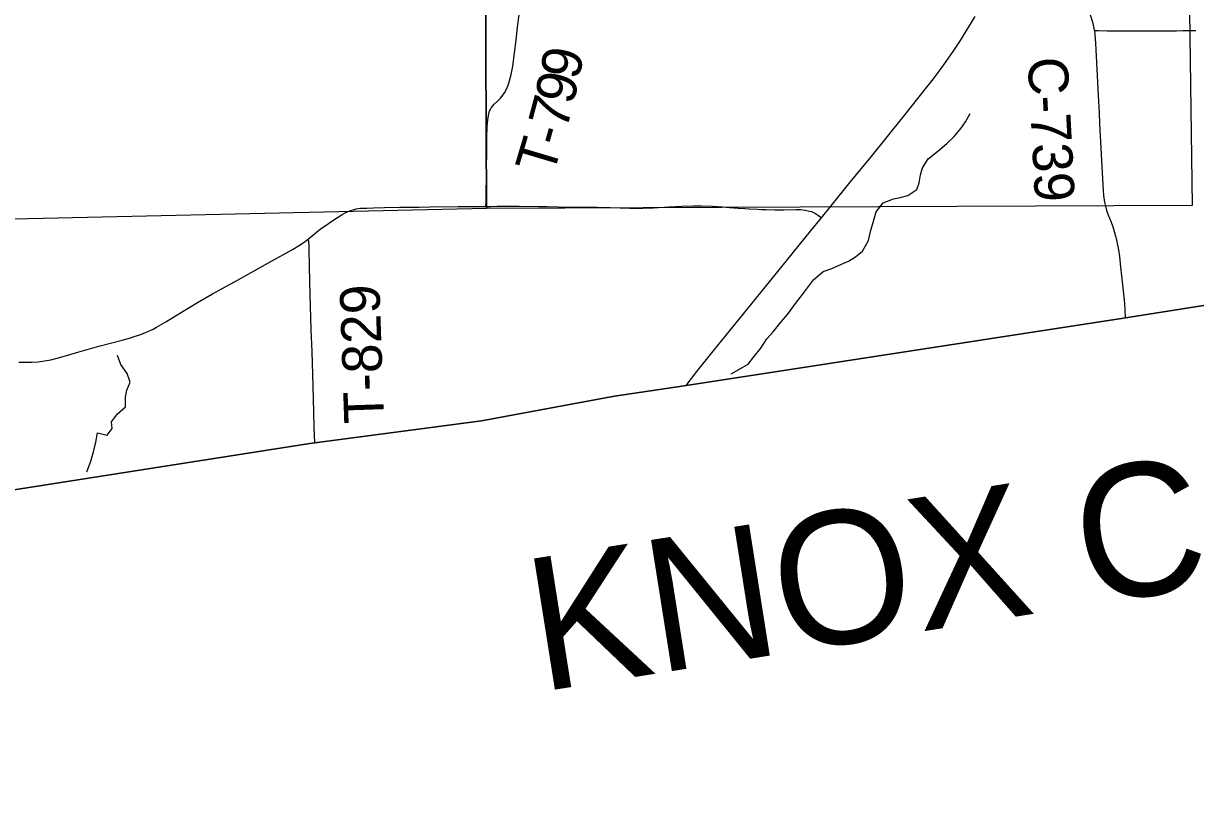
# Model space of a CAD drawing. Extents: x 1874609 to 2204689, y 815661 to 1281160.
# Drawn here: x 2026660 to 2035487, y 930213 to 936005 of the extents above; entities that cross this region are included whole.
import ezdxf

# ---------------------------------------------------------------- set-up
doc = ezdxf.new("R2010")
doc.units = 0
for name, color, linetype in [('GM_X_Adjacent_County', 7, 'Continuous'), ('GM_X_Adjacent_County_Text', 7, 'Continuous'), ('GM_X_County', 7, 'Continuous'), ('GM_X_County_Road', 7, 'Continuous'), ('GM_X_County_Road_Text', 7, 'Continuous'), ('GM_X_Minor_River', 7, 'Continuous'), ('GM_X_Section', 7, 'Continuous'), ('GM_X_State_Route', 7, 'Continuous'), ('GM_X_Township', 7, 'Continuous'), ('GM_X_Township_Road', 7, 'Continuous'), ('GM_X_Township_Road_Text', 7, 'Continuous')]:
    doc.layers.add(name, color=color, linetype=linetype)

msp = doc.modelspace()

# ---------------------------------------------------------------- linework, layer by layer
at = {"layer": 'GM_X_Adjacent_County'}
msp.add_lwpolyline([(2011234.5, 930213.3), (2013857.4, 930619.3), (2016073.2, 930958.1), (2016684.5, 931060.5), (2017738.3, 931178.7), (2023140.4, 931953.7), (2028815.8, 932841.3), (2030108.2, 933013.6), (2031110.9, 933197.6), (2031636.5, 933277.1), (2034944.9, 933785.2), (2038390.6, 934329.5), (2043970.6, 935214.4), (2046246.2, 935556.5), (2048556.5, 935944.3)], dxfattribs=at)
at = {"layer": 'GM_X_County'}
msp.add_lwpolyline([(2046060.4, 953197.3), (2046126.3, 947408.3), (2046149.8, 945341.9), (2046150.4, 945285.9), (2046161.5, 944312), (2046172.3, 943252.1), (2046190, 941523.5), (2046229.9, 937601.3), (2046239.8, 936622.7), (2046246.2, 935556.5), (2043970.6, 935214.4), (2038390.6, 934329.5), (2034944.9, 933785.2), (2031636.5, 933277.1), (2031110.9, 933197.6), (2030108.2, 933013.6), (2028815.8, 932841.3), (2023140.4, 931953.7)], dxfattribs=at)
at = {"layer": 'GM_X_County_Road'}
for points in [[(2034727.3, 935952.5), (2034726.9, 935955.5), (2034715.6, 936003.9), (2034701.5, 936051.4), (2034674.9, 936129.4), (2034634.2, 936237.1), (2034580.5, 936375.1), (2034531.4, 936497), (2034491.7, 936604.1), (2034480.2, 936634.2), (2034469, 936664.2), (2034463.2, 936679.1), (2034457.2, 936693.9), (2034451.5, 936707.9)], [(2034727.3, 935952.5), (2034755.9, 935951.9), (2034821.3, 935950.7), (2034919.5, 935950.5), (2035050.6, 935950.5), (2035116, 935950.5), (2035148.7, 935950.6), (2035229.7, 935950.7), (2035310.6, 935950.4), (2035343.1, 935950.7), (2035392, 935951.5), (2035441, 935952.1), (2035490.1, 935952.7)], [(2034960.1, 933789.5), (2034956.1, 933845.7), (2034953.3, 933895.1), (2034949.1, 933944.2), (2034943.8, 933992.8), (2034930.6, 934105), (2034924.2, 934169.3), (2034916.6, 934250.6), (2034914.8, 934266.9), (2034912.7, 934283.2), (2034907.2, 934315.9), (2034900.2, 934348.2), (2034896.4, 934363.9), (2034892.4, 934379.5), (2034888.5, 934394.7), (2034884.6, 934409.5), (2034868.7, 934463.8), (2034863.7, 934477.4), (2034852.9, 934505.8), (2034829.3, 934566.1), (2034818.9, 934597.1), (2034810.4, 934628.5), (2034804, 934660.5), (2034797.2, 934709), (2034790.5, 934790.6), (2034778.9, 935020.3), (2034766.9, 935249.9), (2034762.3, 935331.6), (2034755.7, 935462.8), (2034746.7, 935659.8), (2034736.9, 935857), (2034731.6, 935922.7), (2034727.3, 935952.5)]]:
    msp.add_lwpolyline(points, dxfattribs=at)
at = {"layer": 'GM_X_Minor_River'}
for points in [[(2031989.5, 933365.4), (2032117.2, 933438.7), (2032161.1, 933494.8), (2032213.1, 933559), (2032259.1, 933629.1), (2032305.1, 933683.2), (2032367, 933757.4), (2032413, 933813.5), (2032473, 933895.7), (2032527, 933963.8), (2032570.9, 934023.9), (2032608.9, 934074), (2032682.9, 934136.2), (2032746.9, 934160.3), (2032821, 934192.4), (2032873, 934214.5), (2032925, 934248.6), (2032979, 934290.8), (2033025, 934370.9), (2033038.9, 934439), (2033056.9, 934499.1), (2033080.8, 934587.2), (2033134.8, 934653.3), (2033212.8, 934683.5), (2033262.8, 934693.6), (2033318.9, 934709.7), (2033388.9, 934753.8), (2033404.8, 934805.9), (2033414.8, 934863.9), (2033430.7, 934918), (2033472.7, 934986.2), (2033546.7, 935042.3), (2033614.7, 935100.4), (2033668.7, 935154.6), (2033718.7, 935214.7), (2033754.7, 935264.8), (2033788.6, 935326.9)], [(2027137.1, 932628.9), (2027168.2, 932709), (2027188.2, 932779.1), (2027204.1, 932851.2), (2027218.1, 932923.3), (2027290.1, 932905.4), (2027328.1, 932955.5), (2027322.1, 933005.5), (2027368, 933065.7), (2027428, 933117.8), (2027428, 933191.9), (2027437.9, 933243.9), (2027463.9, 933304), (2027439.8, 933370), (2027393.7, 933438), (2027367.6, 933504.1)]]:
    msp.add_lwpolyline(points, dxfattribs=at)
at = {"layer": 'GM_X_Section'}
for points in [[(2024693.3, 939774.8), (2027110.1, 939885.9), (2030125.1, 939970.3), (2030146.3, 934612.1), (2024690.4, 934488.6)], [(2035389.4, 939909.3), (2035462.3, 934635.3), (2030146.3, 934612.1), (2030125.1, 939970.3)]]:
    msp.add_lwpolyline(points, close=True, dxfattribs=at)
at = {"layer": 'GM_X_State_Route'}
msp.add_lwpolyline([(2031650.6, 933277.6), (2031730.1, 933383.7), (2031854.6, 933536.2), (2032246.9, 934020.4), (2032587.2, 934441.1), (2032670, 934542.5), (2032742.8, 934631.6), (2032886.9, 934810.4), (2033042.9, 935000.5), (2033290.1, 935306.3), (2033452.8, 935512), (2033483, 935550.6), (2033512.9, 935589.2), (2033590.4, 935694.7), (2033666.2, 935801.6), (2033711.5, 935869.7), (2033826.6, 936057.6)], dxfattribs=at)
at = {"layer": 'GM_X_Township'}
msp.add_lwpolyline([(2046060.4, 953197.3), (2046126.3, 947408.3), (2046149.8, 945341.9), (2046150.4, 945285.9), (2046161.5, 944312), (2046172.3, 943252.1), (2046190, 941523.5), (2046229.9, 937601.3), (2046239.8, 936622.7), (2046246.2, 935556.5), (2043970.6, 935214.4), (2038390.6, 934329.5), (2034944.9, 933785.2), (2031636.5, 933277.1), (2031110.9, 933197.6), (2030108.2, 933013.6), (2028815.8, 932841.3), (2023140.4, 931953.7)], dxfattribs=at)
at = {"layer": 'GM_X_Township_Road'}
for points in [[(2030142.9, 934627.5), (2030143.3, 934658.6), (2030147.4, 934920.8), (2030149.1, 935035.4), (2030150.5, 935149.7), (2030152.7, 935231.2), (2030156.3, 935280), (2030161.5, 935312.2), (2030165.5, 935328), (2030170.8, 935343.4), (2030177.6, 935358.1), (2030185.6, 935372.2), (2030195.2, 935385.4), (2030205.8, 935397.7), (2030229.2, 935420.7), (2030252.6, 935443.5), (2030263.6, 935455.7), (2030273.6, 935468.5), (2030282.6, 935482), (2030298, 935510.6), (2030310.5, 935540.7), (2030320.4, 935571.8), (2030331.8, 935619.6), (2030344.2, 935683.9), (2030359.1, 935781.2), (2030371, 935878.7), (2030381.5, 935976.3), (2030392.6, 936073.6)], [(2030142.9, 934627.5), (2030179.4, 934627.7), (2030228.5, 934628.1), (2030293.9, 934628.3), (2030391.8, 934627.9), (2030538.4, 934626.6), (2030603.7, 934625.5), (2030685.6, 934623.9), (2030767.6, 934622.8), (2030866, 934622.2), (2030980.7, 934621.1), (2031078.8, 934618.5), (2031225.8, 934614.5), (2031323.3, 934615.1), (2031404.9, 934617.8), (2031519.5, 934623.7), (2031617.8, 934629.1), (2031699.8, 934631.3), (2031765.3, 934631.3), (2031846.8, 934628.7), (2031928, 934623.9), (2031976.9, 934620.3), (2032042.4, 934615.1), (2032091.5, 934611.4), (2032124, 934609.7), (2032189.1, 934606.1), (2032221.8, 934604.5), (2032254.3, 934603), (2032319.6, 934601.2), (2032385, 934601.1), (2032482.8, 934603.7), (2032515.5, 934602.8), (2032548, 934599.3), (2032580.1, 934592.6), (2032595.7, 934587.8), (2032610.7, 934581.4), (2032625, 934573.4), (2032646.1, 934559.3), (2032670, 934542.5)], [(2028805.6, 934383.1), (2028821.6, 934395.6), (2028898.1, 934457.2), (2028924, 934476.4), (2028991, 934522.4), (2029060.1, 934565.7), (2029088.7, 934581.6), (2029118.4, 934595.1), (2029149.5, 934605.2), (2029165.4, 934608.8), (2029197.8, 934613.1), (2029246.9, 934615.2), (2029295.9, 934616.8), (2029377.7, 934619), (2029492.2, 934620.4), (2029557.6, 934620.4), (2029606.5, 934620.9), (2029639.1, 934620.9), (2029720.7, 934623.1), (2029934, 934625.4), (2030032.3, 934626.5), (2030130.4, 934627.4), (2030142.9, 934627.5)], [(2027637.2, 933704), (2027662.7, 933717.4), (2027733.3, 933759), (2027817.1, 933810.4), (2027971, 933904.6), (2028084.7, 933969.9), (2028272, 934071.9), (2028500.6, 934200.4), (2028686.9, 934303.4), (2028742.8, 934337.3), (2028782.9, 934365.5), (2028805.6, 934383.1)], [(2028855.3, 932847.9), (2028849.6, 932962.2), (2028845.9, 933076.7), (2028843.4, 933175), (2028841, 933273.4), (2028833.2, 933535.7), (2028827.5, 933699.6), (2028819.8, 933961.6), (2028815.2, 934174.4), (2028812.4, 934305.5), (2028810.8, 934338.3), (2028808.9, 934354.5), (2028805.6, 934383.1)], [(2027500.8, 933649), (2027528.1, 933657.9), (2027574.2, 933674.9), (2027619.2, 933694.6), (2027637.2, 933704)], [(2026624.9, 933455.5), (2026673.1, 933453.2), (2026721.5, 933454), (2026769.8, 933457.6), (2026818.1, 933463.7), (2026866, 933472.3), (2026913.6, 933483.6), (2026976.3, 933501.9), (2027070.6, 933529.3), (2027228.3, 933573.9), (2027402.7, 933620), (2027465.8, 933637.7), (2027500.8, 933649)]]:
    msp.add_lwpolyline(points, dxfattribs=at)

# ---------------------------------------------------------------- texts
at = {"layer": 'GM_X_Adjacent_County_Text'}
msp.add_text('KNOX COUNTY', height=1000, rotation=8.99869, dxfattribs=at).set_placement((2030553.6, 930971.1))
at = {"layer": 'GM_X_County_Road_Text'}
msp.add_text('C-739', height=300, rotation=272.99873, dxfattribs=at).set_placement((2034222.1, 935745.5))
at = {"layer": 'GM_X_Township_Road_Text'}
for s, rotation, p in [('9', 78.80009, (2030841.6, 935573.3)), ('9', 77.26041, (2030799, 935384.4)), ('7', 75.10205, (2030748.5, 935193.9)), ('T', 73.40173, (2030647.5, 934851.2)), ('-', 73.84601, (2030712.3, 935068.6)), ('T-829', 91.94665, (2029375.9, 932996.8))]:
    msp.add_text(s, height=300, rotation=rotation, dxfattribs=at).set_placement(p)

doc.saveas('drawing.dxf')
